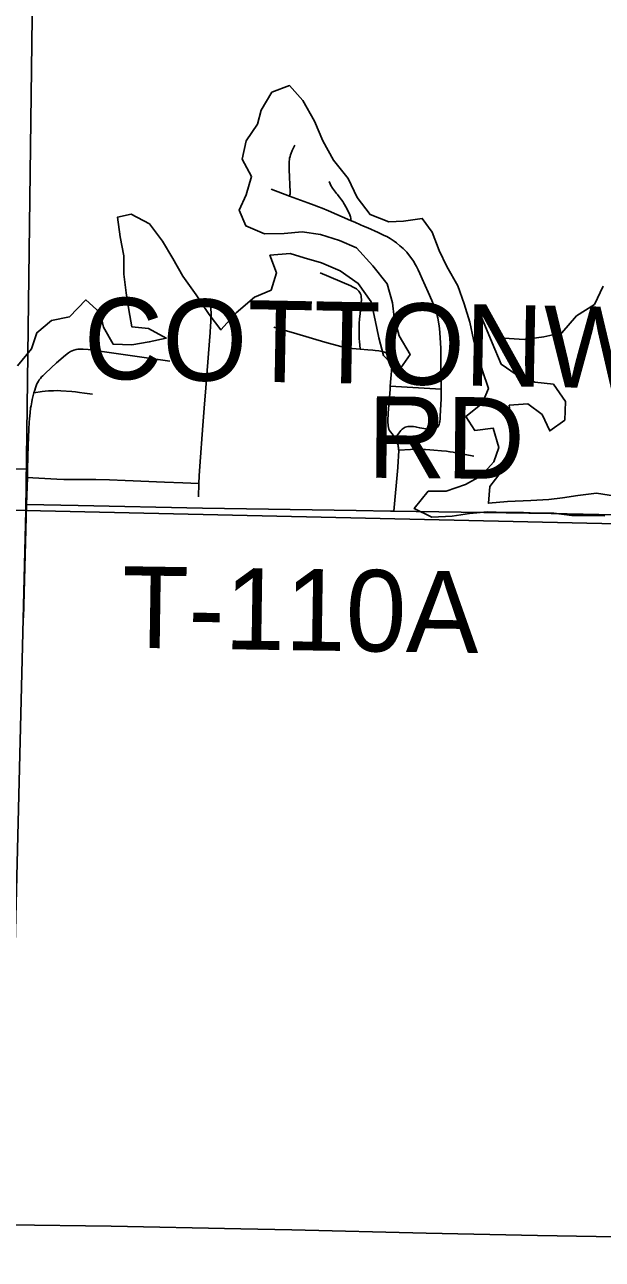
# Model space of a CAD drawing. Extents: x -38.1 to 35.9, y -2.7 to 28.5.
# Drawn here: x 24.124 to 24.527, y 17.464 to 18.326 of the extents above; entities that cross this region are included whole.
import ezdxf

# ---------------------------------------------------------------- set-up
doc = ezdxf.new("R2010")
doc.units = 0
for name, color, linetype in [('GM_X_Interchange_Ramps', 7, 'Continuous'), ('GM_X_Interstate_Shield', 7, 'Continuous'), ('GM_X_Major_River_Text', 7, 'Continuous'), ('GM_X_Minor_Lake', 7, 'Continuous'), ('GM_X_US_Route', 7, 'Continuous')]:
    doc.layers.add(name, color=color, linetype=linetype)

msp = doc.modelspace()

# ---------------------------------------------------------------- linework, layer by layer
at = {"layer": 'GM_X_Interchange_Ramps'}
msp.add_lwpolyline([(23.60987, 17.49479), (23.69774, 17.49333), (23.72744, 17.49292), (23.74247, 17.49271), (23.79902, 17.4921), (23.81792, 17.49196), (23.84687, 17.49174), (23.88726, 17.49108), (23.89352, 17.49103), (23.98605, 17.49027), (24.02085, 17.48958), (24.0275, 17.48949), (24.03247, 17.48943), (24.10163, 17.48848), (24.11302, 17.48833), (24.18437, 17.48741), (24.27496, 17.48562), (24.31037, 17.48475), (24.40417, 17.48244), (24.48182, 17.48095), (24.52284, 17.48016), (24.61517, 17.47824)], dxfattribs=at)
at = {"layer": 'GM_X_Interstate_Shield'}
for points in [[(24.11887, 18.08759), (24.12872, 18.09945), (24.13247, 18.11072), (24.1426, 18.11915), (24.15521, 18.12182), (24.16657, 18.13363), (24.17656, 18.12461), (24.17893, 18.11467), (24.18579, 18.10271), (24.19869, 18.10232), (24.2109, 18.10424), (24.22276, 18.10693), (24.21042, 18.11375), (24.19868, 18.11485), (24.19675, 18.12667), (24.19483, 18.13849), (24.19331, 18.15144), (24.19331, 18.16434), (24.19067, 18.1777), (24.1888, 18.19142), (24.19835, 18.19341), (24.21106, 18.18659), (24.2202, 18.17456), (24.22744, 18.16258), (24.2343, 18.15023), (24.24378, 18.13705), (24.25287, 18.1235), (24.26091, 18.11264), (24.27151, 18.12447), (24.28437, 18.13548), (24.29592, 18.14046), (24.29969, 18.15249), (24.29512, 18.16477), (24.30921, 18.16587), (24.31899, 18.16293), (24.33105, 18.15954), (24.34417, 18.15384), (24.35683, 18.14512), (24.36594, 18.13233), (24.3686, 18.11935), (24.37128, 18.10712), (24.37433, 18.09489), (24.38502, 18.08395), (24.39296, 18.09548), (24.38537, 18.10861), (24.38195, 18.12123), (24.38073, 18.13151), (24.37695, 18.14491), (24.36707, 18.15734), (24.35566, 18.16982), (24.34366, 18.1751), (24.33049, 18.17929), (24.31763, 18.18118), (24.30507, 18.18003), (24.29138, 18.17967), (24.27826, 18.18537), (24.27364, 18.19614), (24.27852, 18.207), (24.28232, 18.21979), (24.27583, 18.23174), (24.27849, 18.24457), (24.28643, 18.2561), (24.289, 18.26589), (24.29659, 18.27857)], [(24.29659, 18.27857), (24.30888, 18.28314), (24.31807, 18.27263), (24.32638, 18.25834), (24.33205, 18.24451), (24.33962, 18.23101), (24.34988, 18.21819), (24.35595, 18.2051), (24.36509, 18.19307), (24.37823, 18.18813), (24.3885, 18.18859), (24.40147, 18.19048), (24.4084, 18.18079), (24.41334, 18.16813), (24.41871, 18.15696), (24.42629, 18.14346), (24.43085, 18.1308), (24.43465, 18.11817), (24.43733, 18.10594), (24.44008, 18.09599), (24.44352, 18.08413), (24.44772, 18.07186), (24.44323, 18.06137), (24.43194, 18.05221), (24.43811, 18.04254), (24.45107, 18.04406), (24.45485, 18.03067), (24.45151, 18.02052), (24.44249, 18.01092), (24.43167, 18.00478), (24.41825, 18.00024), (24.40571, 18.00023), (24.39585, 17.988), (24.40821, 17.98194), (24.42228, 17.98267), (24.43449, 17.98459), (24.44706, 17.98574), (24.45921, 17.98538), (24.47212, 17.98538), (24.4816, 17.98472), (24.49337, 17.98476), (24.50586, 17.98325), (24.51878, 17.98325), (24.52902, 17.98295)], [(24.53627, 17.99678), (24.52303, 17.99868), (24.51007, 17.99717), (24.49939, 17.99558), (24.48986, 17.99435), (24.4773, 17.99358), (24.46095, 17.99292), (24.44762, 17.99179), (24.44873, 18.00352), (24.45662, 18.01354), (24.46185, 18.02325), (24.46455, 18.03759), (24.46369, 18.0471), (24.46218, 18.06005), (24.47513, 18.06119), (24.48516, 18.05369), (24.49051, 18.04214), (24.501, 18.0498), (24.50138, 18.0627), (24.493, 18.07471), (24.48013, 18.07622), (24.46699, 18.08154), (24.45657, 18.08868), (24.45018, 18.10367), (24.44522, 18.11596), (24.4399, 18.12863), (24.45028, 18.11998), (24.45863, 18.10683), (24.47266, 18.10604), (24.48639, 18.10792), (24.499, 18.11058), (24.50923, 18.12242), (24.52162, 18.13041), (24.52769, 18.14313)]]:
    msp.add_lwpolyline(points, dxfattribs=at)
at = {"layer": 'GM_X_Major_River_Text'}
for p, q in [((24.37918, 18.07353), (24.4147, 18.0714)), ((24.12585, 18.00974), (24.12601, 18.01552)), ((24.12534, 17.99093), (24.12585, 18.00974)), ((24.1232, 17.91188), (24.12534, 17.99093))]:
    msp.add_line(p, q, dxfattribs=at)
for points in [[(24.30886, 18.20608), (24.3091, 18.20688), (24.30926, 18.20769), (24.30932, 18.20884), (24.30866, 18.22459), (24.30858, 18.22653), (24.30857, 18.22737), (24.30855, 18.22843), (24.30855, 18.22939), (24.30863, 18.2304), (24.30874, 18.23142), (24.30891, 18.2324), (24.30926, 18.23369), (24.30962, 18.23489), (24.30997, 18.2359), (24.31075, 18.23772), (24.31147, 18.23931), (24.31252, 18.24146)], [(24.38277, 18.0373), (24.38514, 18.04065), (24.38591, 18.04166), (24.38658, 18.04248), (24.38756, 18.04348), (24.38805, 18.04389), (24.38885, 18.04439), (24.38964, 18.04479), (24.39053, 18.04506), (24.39138, 18.04524), (24.39249, 18.04536), (24.39344, 18.04539), (24.3946, 18.04532), (24.39546, 18.04521), (24.39669, 18.04498), (24.3976, 18.04474), (24.39976, 18.04434), (24.40531, 18.04352), (24.4061, 18.04343), (24.40686, 18.04338), (24.40806, 18.04338), (24.40904, 18.04346), (24.41026, 18.04375), (24.4113, 18.04426), (24.41207, 18.04485), (24.41267, 18.04562), (24.41319, 18.04675), (24.41351, 18.04802), (24.41364, 18.04885), (24.41388, 18.05071), (24.41404, 18.05225), (24.41448, 18.06089), (24.4146, 18.0644), (24.4147, 18.07038), (24.4147, 18.0714), (24.41455, 18.09037), (24.41448, 18.09554), (24.41438, 18.09958), (24.41402, 18.10726), (24.41351, 18.11357), (24.41312, 18.1169), (24.4127, 18.11948), (24.41239, 18.12106), (24.41199, 18.12274), (24.41149, 18.1246), (24.41101, 18.1261), (24.41043, 18.12775), (24.40985, 18.12923), (24.40816, 18.13309), (24.40556, 18.13897), (24.40131, 18.14839), (24.39971, 18.15196), (24.39853, 18.1546), (24.39739, 18.157), (24.39684, 18.15805), (24.39533, 18.16064), (24.39421, 18.16231), (24.39198, 18.16532), (24.39062, 18.16688), (24.38969, 18.16784), (24.38816, 18.16937), (24.38592, 18.17142), (24.38351, 18.17344), (24.38196, 18.17457), (24.3792, 18.17636), (24.3767, 18.17775), (24.375, 18.17859), (24.37071, 18.18058), (24.36349, 18.18379), (24.36044, 18.18513), (24.35841, 18.18603), (24.35447, 18.18775), (24.35148, 18.18904), (24.33609, 18.19564), (24.33165, 18.19749), (24.32916, 18.19848), (24.3261, 18.19967), (24.32165, 18.2013), (24.30886, 18.20608), (24.29599, 18.21086)], [(24.35148, 18.18904), (24.35166, 18.1898), (24.35166, 18.19066), (24.35148, 18.19164), (24.35127, 18.19228), (24.35096, 18.19302), (24.34879, 18.19737), (24.34649, 18.20137), (24.34595, 18.20224), (24.3451, 18.20352), (24.34448, 18.20438), (24.34379, 18.2053), (24.34282, 18.20649), (24.34235, 18.20703), (24.34163, 18.20788), (24.34093, 18.20874), (24.33956, 18.21056), (24.33878, 18.21166), (24.33775, 18.21334), (24.33719, 18.21446), (24.33651, 18.21616)], [(24.35813, 18.09923), (24.35783, 18.10221), (24.35762, 18.10429), (24.35744, 18.10661), (24.35735, 18.109), (24.35734, 18.11108), (24.35736, 18.11286), (24.35742, 18.11462), (24.35755, 18.11735), (24.35773, 18.12012), (24.35861, 18.12818), (24.35883, 18.13072), (24.35894, 18.13213), (24.359, 18.13307), (24.35899, 18.13419), (24.35892, 18.13535), (24.35876, 18.13649), (24.35854, 18.1373), (24.35819, 18.13819), (24.35777, 18.13895), (24.35719, 18.13976), (24.35614, 18.14076), (24.35555, 18.14123), (24.35477, 18.14173), (24.35279, 18.14275), (24.35159, 18.14332), (24.33025, 18.15242)], [(24.24525, 17.9962), (24.24553, 18.0056), (24.24579, 18.01088), (24.24619, 18.0176), (24.24823, 18.04594), (24.24944, 18.06106), (24.2501, 18.06933), (24.25105, 18.08124), (24.25292, 18.10507), (24.25339, 18.1109), (24.25373, 18.1154), (24.25387, 18.11795), (24.25398, 18.12046), (24.25407, 18.12338), (24.25405, 18.12503), (24.25398, 18.12658), (24.25389, 18.12805), (24.2537, 18.12971), (24.2531, 18.13396)], [(24.29788, 18.11458), (24.3139, 18.10993), (24.33356, 18.10407), (24.34476, 18.10117), (24.34712, 18.10061), (24.34897, 18.10023), (24.35268, 18.09969), (24.35813, 18.09923)], [(24.13049, 18.06881), (24.13099, 18.0707), (24.13143, 18.0723), (24.13192, 18.07367), (24.13245, 18.07498), (24.13294, 18.07585), (24.13354, 18.07687), (24.13421, 18.07785), (24.13495, 18.07883), (24.13578, 18.07982), (24.13665, 18.08071), (24.13859, 18.08257), (24.1463, 18.08971), (24.15245, 18.09501), (24.15453, 18.09665), (24.15603, 18.09758), (24.15713, 18.09811), (24.15832, 18.09855), (24.15987, 18.09895), (24.16118, 18.09914), (24.16296, 18.09931), (24.16477, 18.09926), (24.16832, 18.09889), (24.22537, 18.09083)], [(24.37918, 18.07353), (24.38017, 18.08666), (24.38028, 18.08925), (24.38029, 18.09011), (24.38026, 18.09096), (24.38015, 18.09203), (24.37994, 18.0931), (24.37948, 18.09418), (24.37902, 18.09483), (24.37834, 18.09554), (24.37771, 18.09596), (24.37659, 18.09653), (24.37506, 18.09707), (24.37342, 18.09754), (24.37108, 18.09795), (24.36854, 18.09829), (24.36698, 18.09846), (24.36359, 18.09878), (24.35813, 18.09923)], [(24.38277, 18.0373), (24.38175, 18.03866), (24.38128, 18.03919), (24.38042, 18.04019), (24.37922, 18.04158), (24.37861, 18.04245), (24.37818, 18.0434), (24.37788, 18.04448), (24.37766, 18.04581), (24.37759, 18.04657), (24.37753, 18.04783), (24.37753, 18.04908), (24.37779, 18.05486), (24.37899, 18.07098), (24.37918, 18.07353)], [(24.12601, 18.01552), (24.12647, 18.03227), (24.12694, 18.04329), (24.12719, 18.04837), (24.12736, 18.05069), (24.12772, 18.05479), (24.12814, 18.0582), (24.1284, 18.05976), (24.12889, 18.06241), (24.12926, 18.06412), (24.13049, 18.06881)], [(24.13049, 18.06881), (24.13617, 18.06959), (24.13832, 18.06985), (24.1406, 18.07008), (24.14407, 18.07023), (24.1467, 18.07028), (24.14925, 18.07016), (24.15695, 18.06962), (24.15941, 18.06939), (24.16217, 18.06906), (24.16576, 18.06858), (24.17129, 18.06775)], [(24.38507, 18.02883), (24.38498, 18.02957), (24.38482, 18.03072), (24.38471, 18.0314), (24.38456, 18.03228), (24.38429, 18.03337), (24.38388, 18.03472), (24.38353, 18.03565), (24.38322, 18.03636), (24.38277, 18.0373)], [(24.38161, 17.98628), (24.38435, 18.01668), (24.3847, 18.02112), (24.38489, 18.02442), (24.38507, 18.02883)], [(24.38507, 18.02883), (24.39337, 18.02931), (24.39586, 18.02941), (24.39882, 18.02938), (24.40128, 18.0293), (24.4037, 18.0292), (24.40685, 18.029), (24.40962, 18.02879), (24.41482, 18.02835), (24.41838, 18.02799), (24.42083, 18.02765), (24.42303, 18.02728), (24.4262, 18.02669), (24.42917, 18.02611), (24.43144, 18.02567), (24.43756, 18.02448)], [(24.06005, 18.01151), (24.06175, 18.01294), (24.06319, 18.01393), (24.06456, 18.01465), (24.06604, 18.01521), (24.06759, 18.01563), (24.06914, 18.01588), (24.07167, 18.01609), (24.07519, 18.01615), (24.12601, 18.01552)], [(24.12585, 18.00974), (24.12979, 18.0095), (24.14634, 18.00848), (24.15141, 18.00827), (24.15401, 18.00821), (24.15995, 18.00821), (24.16733, 18.00828), (24.17376, 18.00824), (24.18325, 18.00805), (24.19418, 18.00763), (24.22152, 18.00634), (24.23426, 18.00588), (24.24553, 18.0056)], [(24.12534, 17.99093), (24.16125, 17.9901), (24.24809, 17.98827), (24.35544, 17.98668), (24.37928, 17.98632), (24.38161, 17.98628)], [(24.38161, 17.98628), (24.49153, 17.98462), (24.55813, 17.98317), (24.57201, 17.98306)]]:
    msp.add_lwpolyline(points, dxfattribs=at)
at = {"layer": 'GM_X_US_Route'}
for points in [[(23.1004, 19.00392), (24.1377, 18.98286), (24.12478, 17.98667), (23.0833, 18.00706)], [(25.13825, 18.96301), (25.12451, 17.96419), (24.12478, 17.98667), (24.1377, 18.98286)], [(24.12478, 17.98667), (24.09987, 16.98408), (23.08302, 17.00397), (23.0833, 18.00706)], [(24.12478, 17.98667), (25.12451, 17.96419), (25.10497, 16.96445), (24.09987, 16.98408)]]:
    msp.add_lwpolyline(points, close=True, dxfattribs=at)

# ---------------------------------------------------------------- texts
at = {"layer": 'GM_X_Minor_Lake'}
for s, rotation, p in [('COTTONWOOD', 358.9478, (24.16479, 18.07874)), ('RD', 359.51791, (24.36308, 18.00955)), ('T-110A', 359.14147, (24.19149, 17.89101))]:
    msp.add_text(s, height=0.056818, rotation=rotation, dxfattribs=at).set_placement(p)

doc.saveas('drawing.dxf')
